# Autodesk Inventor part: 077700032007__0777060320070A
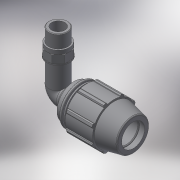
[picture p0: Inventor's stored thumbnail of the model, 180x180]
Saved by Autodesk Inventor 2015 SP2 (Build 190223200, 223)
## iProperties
Created: 2017-02
Part Number: 077700032007__0777060320070A
Material: Generic
Description: PLASSON 90° ELBOW MALE WITH INTEGRAL BRASS THREAD 32-3/4"
Document SubType Name: Modeling
Designer: KIM
Mass: 174.249 g
Surface Area: 431.906 cm^2
Volume: 174.249 cm^3
Density: 1 g/cm^3
Appearance: Default
Author: KIM
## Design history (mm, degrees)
derived "07770.ipt"
feature "Solid1::07770.ipt"
tag "TaggingFeature1"
body "Solid1"
other parameters: "d2" = 32, "d4" = 8.66667, "d5" = 26, "d7" = 64, "d9" = 14.85714, "d11" = 3.46667, "d13" = 120 deg, "d14" = 44.8, "d15" = 12 deg, "d16" = 55.68, "d18" = 1.6, "d19" = 35 deg, "d20" = 17.5 deg, "d21" = 59.52, "d23" = 0, "d25" = 360 deg, "d27" = 1.28, "d33" = 0.64, "d42" = 38.48, "d43" = 1.92, "d46" = 0.96, "d51" = 104, "d68" = 6.93333, "d72" = 79, "d73" = 26.441, "d74" = 18, "d75" = 30.40715, "d76" = 18.5087, "d79" = 10.5764, "d80" = 0.79323, "d83" = 0, "d84" = 0, "d91" = 48, "d93" = 67, "d94" = 26.441, "d95" = 18.5087, "d96" = 6.93333, "d97" = 50 deg, "d98" = 1.73333, "d99" = 54.0096, "d100" = 1.73333, "d101" = 1.73333, "d105" = 1.8, "d106" = 31.7292, "d107" = 18, "d108" = 10.8, "d109" = 0, "d_" = 32, "E_" = 64, "A_" = 104, "l_" = 67, "l_2" = 18, "A_1" = 79, "R_" = 26.441
